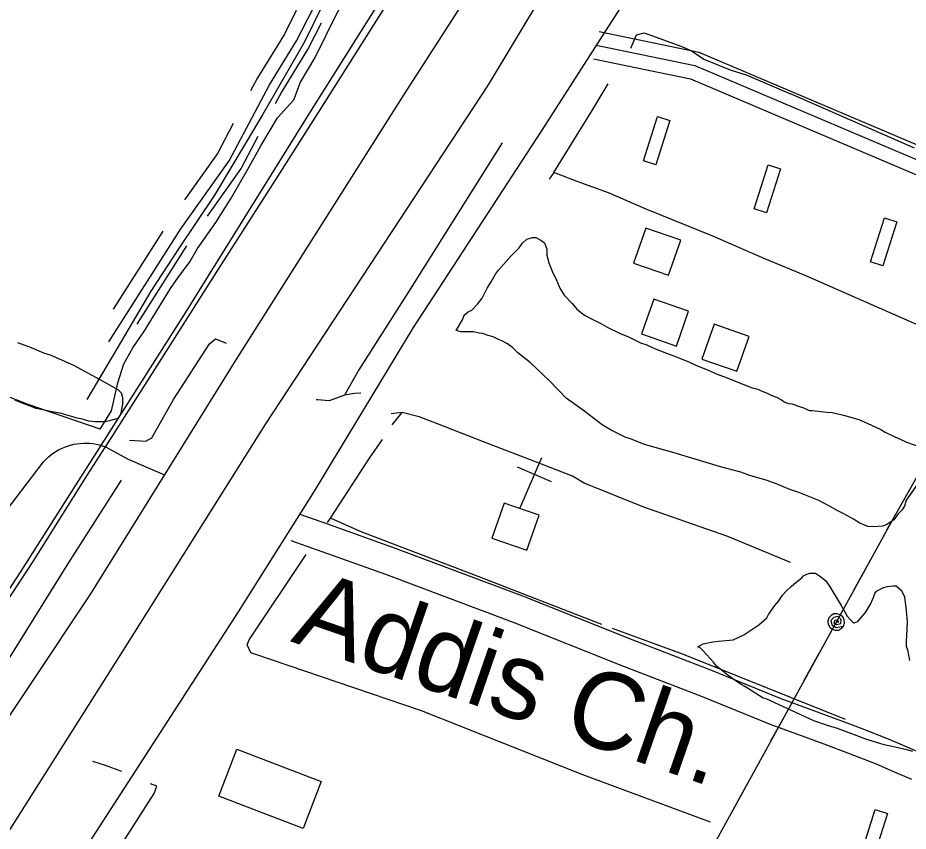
# Model space of a CAD drawing. Extents: x 3297735 to 3335592, y 670436 to 695807.
# Drawn here: x 3304826 to 3305787, y 679947 to 680825 of the extents above; entities that cross this region are included whole.
import ezdxf

# ---------------------------------------------------------------- set-up
doc = ezdxf.new("R2010")
doc.units = 0
for name, color, linetype in [('V-BLDG-OTLN', 7, 'Continuous'), ('V-DTCH-CNTR', 7, 'Continuous'), ('V-RAIL-TRAK', 7, 'Continuous'), ('V-ROAD-CNTR', 7, 'Continuous'), ('V-SITE-OTLN', 7, 'Continuous'), ('V-SITE-OTLN-IDEN', 7, 'Continuous'), ('V-SITE-VEGE', 7, 'Continuous'), ('V-TOPO-SHOR', 7, 'Continuous'), ('V-UTIL-LINE', 7, 'Continuous')]:
    doc.layers.add(name, color=color, linetype=linetype)

msp = doc.modelspace()

# ---------------------------------------------------------------- linework, layer by layer
at = {"layer": 'V-BLDG-OTLN'}
for points in [[(3305501.31, 680670.61), (3305516.49, 680718.26), (3305529.83, 680714.01), (3305514.65, 680666.37)], [(3305620.71, 680618.54), (3305635.89, 680666.18), (3305649.22, 680661.93), (3305634.05, 680614.29)], [(3305746.46, 680561.38), (3305761.63, 680609.02), (3305774.97, 680604.77), (3305759.8, 680557.13)], [(3305490.67, 680560.23), (3305528.43, 680547.04), (3305541.63, 680584.8), (3305503.87, 680597.99)], [(3305499.12, 680483.6), (3305536.88, 680470.41), (3305550.07, 680508.17), (3305512.31, 680521.36)], [(3305564.42, 680456.49), (3305602.18, 680443.29), (3305615.37, 680481.05), (3305577.61, 680494.25)], [(3305350.72, 680301.05), (3305337.64, 680263.26), (3305375.43, 680250.17), (3305388.52, 680287.97)], [(3305133.73, 679949.62), (3305042.61, 679984.66), (3305062.1, 680035.35), (3305153.22, 680000.31)], [(3305736.3, 679922.49), (3305751.47, 679970.13), (3305764.81, 679965.88), (3305749.64, 679918.24)]]:
    msp.add_lwpolyline(points, close=True, dxfattribs=at)
at = {"layer": 'V-DTCH-CNTR'}
msp.add_lwpolyline([(3305175.59, 680897.64), (3305165.1, 680860.04), (3305135.06, 680798.46), (3305089.71, 680720.07), (3305038.01, 680633.51), (3304999.23, 680575.7), (3304969.46, 680529.65), (3304932.68, 680467.67), (3304900.16, 680413.01)], dxfattribs=at)
at = {"layer": 'V-RAIL-TRAK'}
msp.add_lwpolyline([(3304812.9, 680192.87), (3304842.36, 680237.97), (3304900.87, 680331.46), (3304920.4, 680361.71), (3304920.68, 680362.15), (3304978.68, 680453.3), (3305042.48, 680553.75), (3305106.28, 680653.73), (3305158.96, 680736.51), (3305210.69, 680818.37), (3305268.21, 680909.06), (3305324.75, 680997.41), (3305392.93, 681105.78), (3305482.82, 681246.69), (3305532.13, 681324.82), (3305573.7, 681389.93), (3305618.64, 681460.62), (3305635.72, 681490.79)], dxfattribs=at)
at = {"layer": 'V-ROAD-CNTR'}
for points in [[(3304192.85, 679233.42), (3304383.75, 679531.72), (3304520.6, 679750.33), (3304668.87, 679982.13), (3304829.44, 680227.64), (3305006.62, 680506.34), (3305142.65, 680725.33), (3305300.92, 680976.53), (3305510.92, 681300.09), (3305638.29, 681505.23), (3305719.17, 681636.18), (3305863.44, 681851.35), (3306005.21, 682081.23), (3306061.06, 682162.32), (3306330.21, 682595.87), (3306503.15, 682864.6), (3306590.08, 683001.61), (3306814.19, 683347.98), (3307001.23, 683642.45)], [(3306935.72, 683397.47), (3306821.52, 683219.58), (3306763.38, 683128.22), (3306646.62, 682952.6), (3306529.41, 682762.24), (3306445.85, 682630.84), (3306357.8, 682493.74), (3306039.37, 681989.61), (3305799.42, 681614.07), (3305636.13, 681359.51), (3305375.21, 680948.71), (3305242.54, 680742.1), (3305061.27, 680455.59), (3304904.14, 680203.02), (3304778.49, 680014.88), (3304644.66, 679807.27), (3304577.47, 679692.08), (3304453.49, 679500.24), (3304351.46, 679340.12)], [(3304296.8, 679131.01), (3304485.25, 679427.52), (3304643.83, 679677.72), (3304822.05, 679956.18), (3304944.12, 680149.21), (3305093.52, 680386.42), (3305333.93, 680752.5), (3305421.35, 680898.36), (3305571.19, 681134.36), (3305709.91, 681350.87), (3305849.83, 681574.6), (3306021.1, 681837.88), (3306128.36, 682008.28), (3306220.68, 682150.94), (3306399.48, 682433.29), (3306516.46, 682614.36), (3306652.65, 682828.73), (3306746.74, 682982.51), (3306824.47, 683104.14), (3306933.16, 683263.02)], [(3306969.52, 683182.78), (3306796.78, 682899.7), (3306629.03, 682638.88), (3306468.46, 682384.21), (3306342.77, 682184.53), (3306280.53, 682098.94), (3306181.18, 681937.81), (3306004.19, 681667.49), (3305918.92, 681528.25), (3305814.29, 681358.87), (3305644.02, 681099.75), (3305514.04, 680886.82), (3305487.87, 680854.28), (3305391.59, 680703.59), (3305252.58, 680490.45), (3305145.5, 680313.95), (3305063.44, 680183.47), (3304875.21, 679892.41), (3304792.73, 679761.66), (3304683.13, 679590.72), (3304601.25, 679460.93), (3304535.25, 679358.28)], [(3304923.92, 680474.98), (3305001.81, 680597.3), (3305053.92, 680670.5), (3305097.57, 680752.7), (3305126.56, 680799.95), (3305150.59, 680847.12), (3305162.89, 680884.47), (3305163.32, 680911.31)], [(3305126.4, 680832.69), (3305113.47, 680807.29), (3305084.54, 680760.15), (3305077.07, 680746.08)], [(3305153.14, 680819.07), (3305139.66, 680792.61), (3305110.6, 680745.25), (3305103.57, 680732.01)], [(3305453.29, 680810.11), (3305561.21, 680787.92), (3306049.51, 680580.63), (3306850.57, 680238.77)], [(3305450.26, 680795.42), (3305556.72, 680773.53), (3306043.64, 680566.83), (3306844.69, 680224.97)], [(3305447.24, 680780.73), (3305552.23, 680759.14), (3306037.76, 680553.02), (3306838.8, 680211.18)], [(3305058.31, 680710.75), (3305041.13, 680678.4), (3305005.52, 680628.37)], [(3305084.81, 680696.68), (3305066.71, 680662.6), (3305029.96, 680610.97)], [(3304982.42, 680594.78), (3304928.71, 680510.43)], [(3305007.73, 680578.67), (3304954.02, 680494.31)], [(3304800.91, 680276.8), (3304829.29, 680313.92), (3304853.35, 680345.48), (3304855.75, 680348.02), (3304858.3, 680350.42), (3304860.98, 680352.67), (3304863.78, 680354.76), (3304866.7, 680356.69), (3304869.73, 680358.44), (3304872.85, 680360.02), (3304876.06, 680361.41), (3304879.34, 680362.62), (3304882.68, 680363.64), (3304886.08, 680364.46), (3304889.52, 680365.08), (3304892.98, 680365.51), (3304896.47, 680365.73), (3304899.96, 680365.76), (3304903.45, 680365.58), (3304906.92, 680365.2), (3304910.36, 680364.62), (3304913.76, 680363.85), (3304917.11, 680362.88), (3304920.4, 680361.71)], [(3304920.4, 680361.71), (3304944.9, 680348.6), (3304984.07, 680331.51)], [(3305130.29, 680289.06), (3305159.09, 680278.99), (3305233.21, 680252.47), (3305370.51, 680200.76), (3305489.63, 680153.2), (3305575.55, 680120.13), (3305649.68, 680089.96), (3305678.04, 680079.71), (3305706.65, 680069.1), (3305735.18, 680058.27), (3305763.82, 680047.12), (3305783.07, 680038.82), (3305802.09, 680030.8)], [(3305120.39, 680260.75), (3305149.08, 680250.71), (3305222.87, 680224.3), (3305359.66, 680172.79), (3305478.68, 680125.27), (3305564.5, 680092.23), (3305638.92, 680061.95), (3305667.73, 680051.53), (3305696.12, 680041.01), (3305724.42, 680030.26), (3305752.44, 680019.36), (3305771.31, 680011.22), (3305790.54, 680003.11)]]:
    msp.add_lwpolyline(points, dxfattribs=at)
at = {"layer": 'V-SITE-OTLN'}
for p, q in [((3305367.85, 680295.12), (3305391.49, 680350.26)), ((3305401.99, 680324), (3305365.23, 680339.76))]:
    msp.add_line(p, q, dxfattribs=at)
at = {"layer": 'V-SITE-VEGE'}
for points in [[(3305809.18, 680338.47), (3305785.03, 680304.04), (3305783.12, 680297.67), (3305780.23, 680293.24), (3305776.35, 680289.3), (3305771.52, 680282.9), (3305768.11, 680280.43), (3305763.25, 680277.46), (3305759.35, 680275.96), (3305749.58, 680275.39), (3305743.71, 680275.83), (3305734.88, 680279.18), (3305728, 680283.52), (3305717.68, 680289.3), (3305711.3, 680292.66), (3305702.95, 680297.48), (3305697.54, 680300.37), (3305690.67, 680303.74), (3305669.09, 680312.36), (3305659.28, 680315.69), (3305645.55, 680321.45), (3305634.76, 680325.27), (3305616.13, 680330.98), (3305606.33, 680334.32), (3305584.28, 680340), (3305569.08, 680344.76), (3305534.29, 680355.22), (3305502.43, 680364.24), (3305487.22, 680370.47), (3305482.32, 680371.9), (3305465.63, 680380.07), (3305456.79, 680385.37), (3305438.09, 680399.88), (3305426.29, 680408.09), (3305417.92, 680414.38), (3305400.17, 680432.81), (3305378.98, 680452.67), (3305365.69, 680463.31), (3305359.77, 680469.13), (3305354.36, 680473), (3305348.96, 680475.89), (3305345.52, 680477.32), (3305339.14, 680480.69), (3305333.75, 680482.11), (3305327.38, 680484.02), (3305323.95, 680484.48), (3305317.59, 680485.89), (3305303.9, 680485.77), (3305299, 680487.2), (3305305.74, 680498.99), (3305307.66, 680503.89), (3305312.03, 680507.35), (3305315.92, 680509.34), (3305322.23, 680515.75), (3305327.06, 680522.15), (3305332.35, 680532.95), (3305336.69, 680539.83), (3305341.51, 680548.18), (3305344.89, 680552.61), (3305358.45, 680567.88), (3305367.18, 680576.75), (3305370.56, 680581.67), (3305375.41, 680586.11), (3305377.85, 680586.62), (3305381.26, 680587.62), (3305385.18, 680587.66), (3305390.58, 680584.77), (3305394.51, 680581.87), (3305397.02, 680575.05), (3305397.07, 680568.69), (3305399.09, 680560.4), (3305403.58, 680549.68), (3305406.57, 680543.35), (3305411.06, 680533.12), (3305415.52, 680525.33), (3305424.4, 680516.61), (3305429.34, 680510.3), (3305437.7, 680504.01)], [(3305437.7, 680504.01), (3305444.58, 680500.16), (3305455.38, 680494.87), (3305462.75, 680490.53), (3305476, 680484.29), (3305484.34, 680480.94), (3305498.08, 680474.2), (3305504.95, 680471.82), (3305513.29, 680467.98), (3305526.05, 680462.71), (3305535.85, 680459.37), (3305551.06, 680453.14), (3305557.93, 680449.78), (3305571.18, 680444.51), (3305580.99, 680440.19), (3305591.78, 680436.37), (3305599.63, 680433.02), (3305618.76, 680425.36), (3305623.66, 680424.42), (3305630.04, 680421.54), (3305634.94, 680419.62), (3305639.85, 680417.22), (3305644.76, 680415.31), (3305650.16, 680412.42), (3305653.11, 680410.49)], [(3304825.37, 680474.42), (3304840.08, 680469.16), (3304853.33, 680463.41), (3304860.69, 680461.03), (3304885.71, 680449.99), (3304914.2, 680434.59), (3304933.84, 680423.51), (3304937.3, 680420.12), (3304938.8, 680415.24), (3304938.87, 680407.42), (3304936.52, 680396.64), (3304933.13, 680392.21), (3304924.84, 680389.7), (3304919.47, 680388.68), (3304909.21, 680388.59), (3304902.35, 680389.51), (3304894.02, 680391.88), (3304889.61, 680392.83), (3304872.95, 680397.57), (3304862.67, 680399.44), (3304845.53, 680403.21), (3304834.25, 680407.51), (3304822.47, 680412.31)], [(3305653.11, 680410.49), (3305657.52, 680408.57), (3305661.44, 680408.11), (3305670.76, 680404.77), (3305675.17, 680403.34), (3305680.08, 680400.94), (3305683.5, 680400.96), (3305699.16, 680399.14), (3305705.03, 680398.7), (3305714.33, 680396.82), (3305717.28, 680395.87), (3305733.94, 680391.12), (3305742.77, 680387.28), (3305757.49, 680380.56), (3305762.41, 680377.67), (3305772.72, 680372.38), (3305778.6, 680369.99), (3305785.48, 680366.62), (3305800.68, 680361.37)], [(3305792.2, 680032.77), (3305785.82, 680034.67), (3305773.09, 680037.5), (3305761.34, 680039.84), (3305741.24, 680046.03), (3305728.98, 680050.81), (3305710.83, 680057.51), (3305700.05, 680060.84), (3305685.34, 680066.09), (3305633.81, 680089.61), (3305630.38, 680090.56), (3305613.66, 680101.18), (3305603.84, 680106.96), (3305597.94, 680111.31), (3305591.05, 680116.14), (3305584.65, 680121.47), (3305580.22, 680124.85), (3305576.76, 680129.22), (3305565.9, 680141.35), (3305562.45, 680144.75), (3305560, 680145.7), (3305565.84, 680149.18), (3305576.09, 680151.22), (3305582.44, 680151.76), (3305598.07, 680153.36), (3305609.76, 680158.83), (3305619.48, 680165.27), (3305625.8, 680169.72), (3305634.54, 680177.13), (3305636.46, 680180.57), (3305643.22, 680190.4), (3305647.58, 680195.33), (3305651.44, 680201.72), (3305654.83, 680205.66), (3305660.65, 680211.08), (3305665.99, 680215.53), (3305672.31, 680220.47), (3305674.25, 680222.44), (3305677.65, 680224.43), (3305681.06, 680225.43), (3305686.93, 680225.48), (3305691.35, 680222.59), (3305697.75, 680217.26), (3305702.2, 680211.43), (3305714.6, 680190.51), (3305719.07, 680182.73), (3305721.06, 680178.84), (3305725, 680174.96), (3305726.48, 680173.01), (3305728.45, 680171.56), (3305732.84, 680173.07), (3305741.06, 680182.91), (3305746.37, 680191.76), (3305749.73, 680199.12), (3305751.16, 680203.53), (3305753.09, 680205.99), (3305759.91, 680209.47), (3305764.3, 680210.98), (3305770.65, 680211.52), (3305774.07, 680211.55), (3305779.98, 680206.71), (3305782.97, 680199.89), (3305785.05, 680184.75), (3305786.13, 680173.03), (3305785.28, 680157.86), (3305784.84, 680151.99), (3305784.88, 680146.62), (3305786.38, 680142.72), (3305788.44, 680131)]]:
    msp.add_lwpolyline(points, dxfattribs=at)
at = {"layer": 'V-TOPO-SHOR'}
for p, q in [((3305793.81, 680684.37), (3305660.05, 680742.72)), ((3305229.99, 680385.45), (3305240.58, 680398.94)), ((3305196.4, 680269.98), (3305163.2, 680284.85))]:
    msp.add_line(p, q, dxfattribs=at)
for points in [[(3304914.58, 680380.82), (3304926.84, 680400.65), (3304933.56, 680430.92), (3304940.12, 680451.27), (3304949.72, 680468.47), (3304962.44, 680486.85), (3304990.52, 680532.87), (3304998.78, 680544.51), (3305011.48, 680561.66), (3305019.79, 680575.77), (3305039.5, 680603.96), (3305056.08, 680630.33), (3305073.99, 680661.65), (3305088.06, 680686.83), (3305105.95, 680716.91), (3305123.65, 680736.44), (3305130.8, 680755.54), (3305146.76, 680781.93), (3305169.26, 680828.05), (3305189.1, 680863.67), (3305197.57, 680887.09), (3305221.79, 680925.11)], [(3305487.47, 680792.31), (3305493.92, 680806.46), (3305502.02, 680808.8), (3305542.68, 680793.84), (3305553.15, 680789.32), (3305566.63, 680780.4), (3305594.95, 680768.75), (3305612.22, 680763.49), (3305660.05, 680742.72)], [(3305404.54, 680657.96), (3305446, 680724.83), (3305463.24, 680753.67)], [(3305348.62, 680690.06), (3305247.61, 680529.02), (3305193.94, 680444.77), (3305178.3, 680417.39)], [(3305675.94, 680546.56), (3305632.34, 680564.72), (3305576.34, 680589.26), (3305504.3, 680618.41), (3305463.68, 680635.85), (3305429.79, 680648.22), (3305404.54, 680657.96), (3305399.45, 680650.61)], [(3304914.58, 680380.82), (3304836.76, 680407.58), (3304666.22, 680473.71), (3304470.45, 680549.9), (3304412.48, 680572.88)], [(3306582.01, 680166.18), (3306460.5, 680216.61), (3306275.72, 680293.97), (3306209.73, 680321.65), (3306084.7, 680377.08), (3305932.53, 680439.63), (3305803.67, 680490.77), (3305675.94, 680546.56)], [(3304946.42, 680369.12), (3304963.83, 680367.76), (3304970.24, 680371.35), (3304993.69, 680412.7), (3305032.79, 680472.82), (3305039.23, 680478.52), (3305050.78, 680473.56)], [(3305196.2, 680419.82), (3305189.32, 680419.26), (3305178.3, 680417.39), (3305161.72, 680411.49), (3305149.37, 680412.39), (3305148, 680412.42)], [(3305660.05, 680236.85), (3305592.34, 680265.1), (3305501.73, 680296.44), (3305437.07, 680322.36), (3305424.8, 680330.02), (3305382.92, 680346.24), (3305328.71, 680367.03), (3305278.81, 680386.49), (3305259.1, 680394.28), (3305240.58, 680398.94), (3305228.77, 680397.28)], [(3305160.18, 680280.22), (3305163.2, 680284.85), (3305205.33, 680349.48), (3305219.42, 680369.84)], [(3304703.53, 679958.35), (3304736.63, 680007.47), (3304777.53, 680072.11), (3304797.5, 680103.68), (3304879.6, 680234.94), (3304937.73, 680325.92)], [(3305456.31, 680170.02), (3305322.61, 680221.78), (3305196.4, 680269.98)], [(3305573.48, 679956.48), (3305435.65, 680007.62), (3305261.73, 680076.56), (3305081.5, 680138.06), (3305077.4, 680139.5), (3305073.42, 680147.81), (3305075.58, 680153.27), (3305136.92, 680245.6)], [(3305719.61, 680067.26), (3305544.34, 680137.59), (3305467.91, 680165.7)], [(3304938.13, 680011.32), (3304920.39, 680017.8), (3304906.73, 680022.16)], [(3304888.01, 679853.55), (3304927.56, 679916.73), (3304972.74, 679987.37), (3304975.63, 679995.56), (3304968.8, 679997.74)]]:
    msp.add_lwpolyline(points, dxfattribs=at)
at = {"layer": 'V-UTIL-LINE'}
for points in [[(3307600.59, 683492.75), (3306458.11, 681495.33), (3305771.88, 680286.2), (3305158.59, 679171.27)], [(3305780.46, 680301.31), (3305771.88, 680286.2), (3305763.87, 680271.63)], [(3305744.59, 680236.58), (3305728.2, 680206.79)], [(3305709.41, 680172.62), (3305712.27, 680172.92), (3305710.75, 680174.68), (3305708.02, 680174.33), (3305706.91, 680171.62), (3305709.8, 680169.85), (3305714.33, 680171.04), (3305714.65, 680175.3), (3305711.16, 680178.69), (3305706.71, 680177.64), (3305703.75, 680174.28), (3305704.65, 680169.54), (3305709.31, 680166.61), (3305717.29, 680168.29), (3305718.35, 680171.64), (3305718.05, 680175.13), (3305716.43, 680178.25), (3305713.75, 680180.51), (3305710.4, 680181.57), (3305706.9, 680181.27), (3305703.78, 680179.65), (3305701.52, 680176.96), (3305700.46, 680173.61), (3305700.77, 680170.12), (3305702.38, 680167), (3305705.07, 680164.74), (3305708.42, 680163.68), (3305711.92, 680163.98), (3305715.03, 680165.6), (3305717.29, 680168.29)], [(3305690.61, 680138.45), (3305674.22, 680108.66)], [(3305654.94, 680073.61), (3305638.56, 680043.82)], [(3305619.28, 680008.77), (3305602.89, 679978.98)]]:
    msp.add_lwpolyline(points, dxfattribs=at)

# ---------------------------------------------------------------- texts
at = {"layer": 'V-SITE-OTLN-IDEN'}
msp.add_text('Addis Ch.', height=83, rotation=340.89927, dxfattribs=at).set_placement((3305119.35, 680151.92))

doc.saveas('drawing.dxf')
